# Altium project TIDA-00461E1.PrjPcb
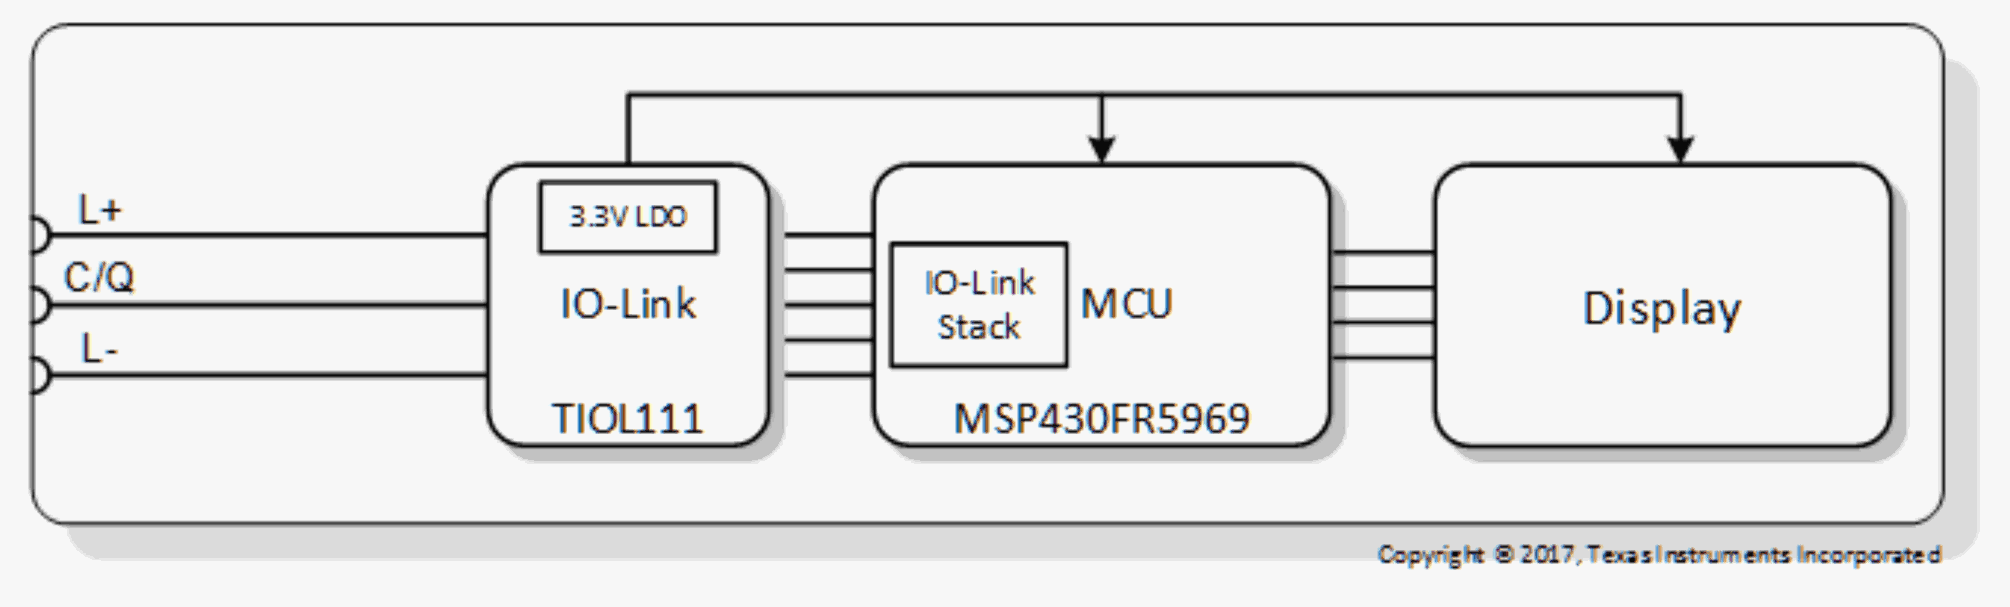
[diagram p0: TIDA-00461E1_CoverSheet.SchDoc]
CopyrightYear: 2016; PCB_Layout: AW; PCB_Rev: E1; PRJ_Customer: Public Release; PRJ_Engineer: AW; PRJ_Number: TIDA-00461; PRJ_Title: IO-Link Firmware Update Reference Design; SCH_Rev: E1; TechSupport: http://www.ti.com/support; TID: TIDA-00461
3 sheets, 79 parts. Net scope: flat (ports and power ports of the same name join across sheets).
Board file: TIDA-00461E1_PCB.PcbDoc
Sheets:
  TIDA-00461E1_CoverSheet.SchDoc
  TIDA-00461E1_Schematic.SchDoc
  TIDA-00461E1_EVM_Hardware.SchDoc

## Sheet TIDA-00461E1_CoverSheet.SchDoc: Block Diagram
size 431 x 279 mm; Date: Not shown in title block; ApprovedBy: Not shown in title block; CheckedBy: Not shown in title block; Author: Not shown in title block; CompanyName: Not shown in title block; DrawnBy: AW; Engineer: Not shown in title block; Organization: Not shown in title block; Address1: Not shown in title block; Address2: Not shown in title block; Address3: Not shown in title block; Address4: Not shown in title block; DocumentNumber: 1; Revision: Use project parameter SCH_Rev; SheetNumber: 1; SheetTotal: 3; PageSetup: Record=PageOptions¦CenterHorizontal=True¦CenterVertical=True¦PrintScale=1.00¦XCorrection=1.00¦YCorrection=1.00¦PrintKind=0¦BorderSize=5000000¦LeftOffset=0¦BottomOffset=0¦Orientation=2¦PaperLength=1000¦PaperWidth=1000¦Scale=100¦PaperSource=15¦PrintQuality=600¦MediaType=1¦DitherType=10¦PaperKind=Letter¦PrintScaleMode=1

## Sheet TIDA-00461E1_Schematic.SchDoc: Schematic
size 431 x 279 mm; Date: Not shown in title block; ApprovedBy: Not shown in title block; CheckedBy: Not shown in title block; Author: Not shown in title block; CompanyName: Not shown in title block; DrawnBy: AW; Engineer: Not shown in title block; Organization: Not shown in title block; Address1: Not shown in title block; Address2: Not shown in title block; Address3: Not shown in title block; Address4: Not shown in title block; DocumentNumber: 2; Revision: Use project parameter SCH_Rev; SheetNumber: 2; SheetTotal: 3; PageSetup: Record=PageOptions¦CenterHorizontal=True¦CenterVertical=True¦PrintScale=1.00¦XCorrection=1.00¦YCorrection=1.00¦PrintKind=0¦BorderSize=5000000¦LeftOffset=0¦BottomOffset=0¦Orientation=2¦PaperLength=1000¦PaperWidth=1000¦Scale=100¦PaperSource=15¦PrintQuality=600¦MediaType=1¦DitherType=10¦PaperKind=Letter¦PrintScaleMode=1
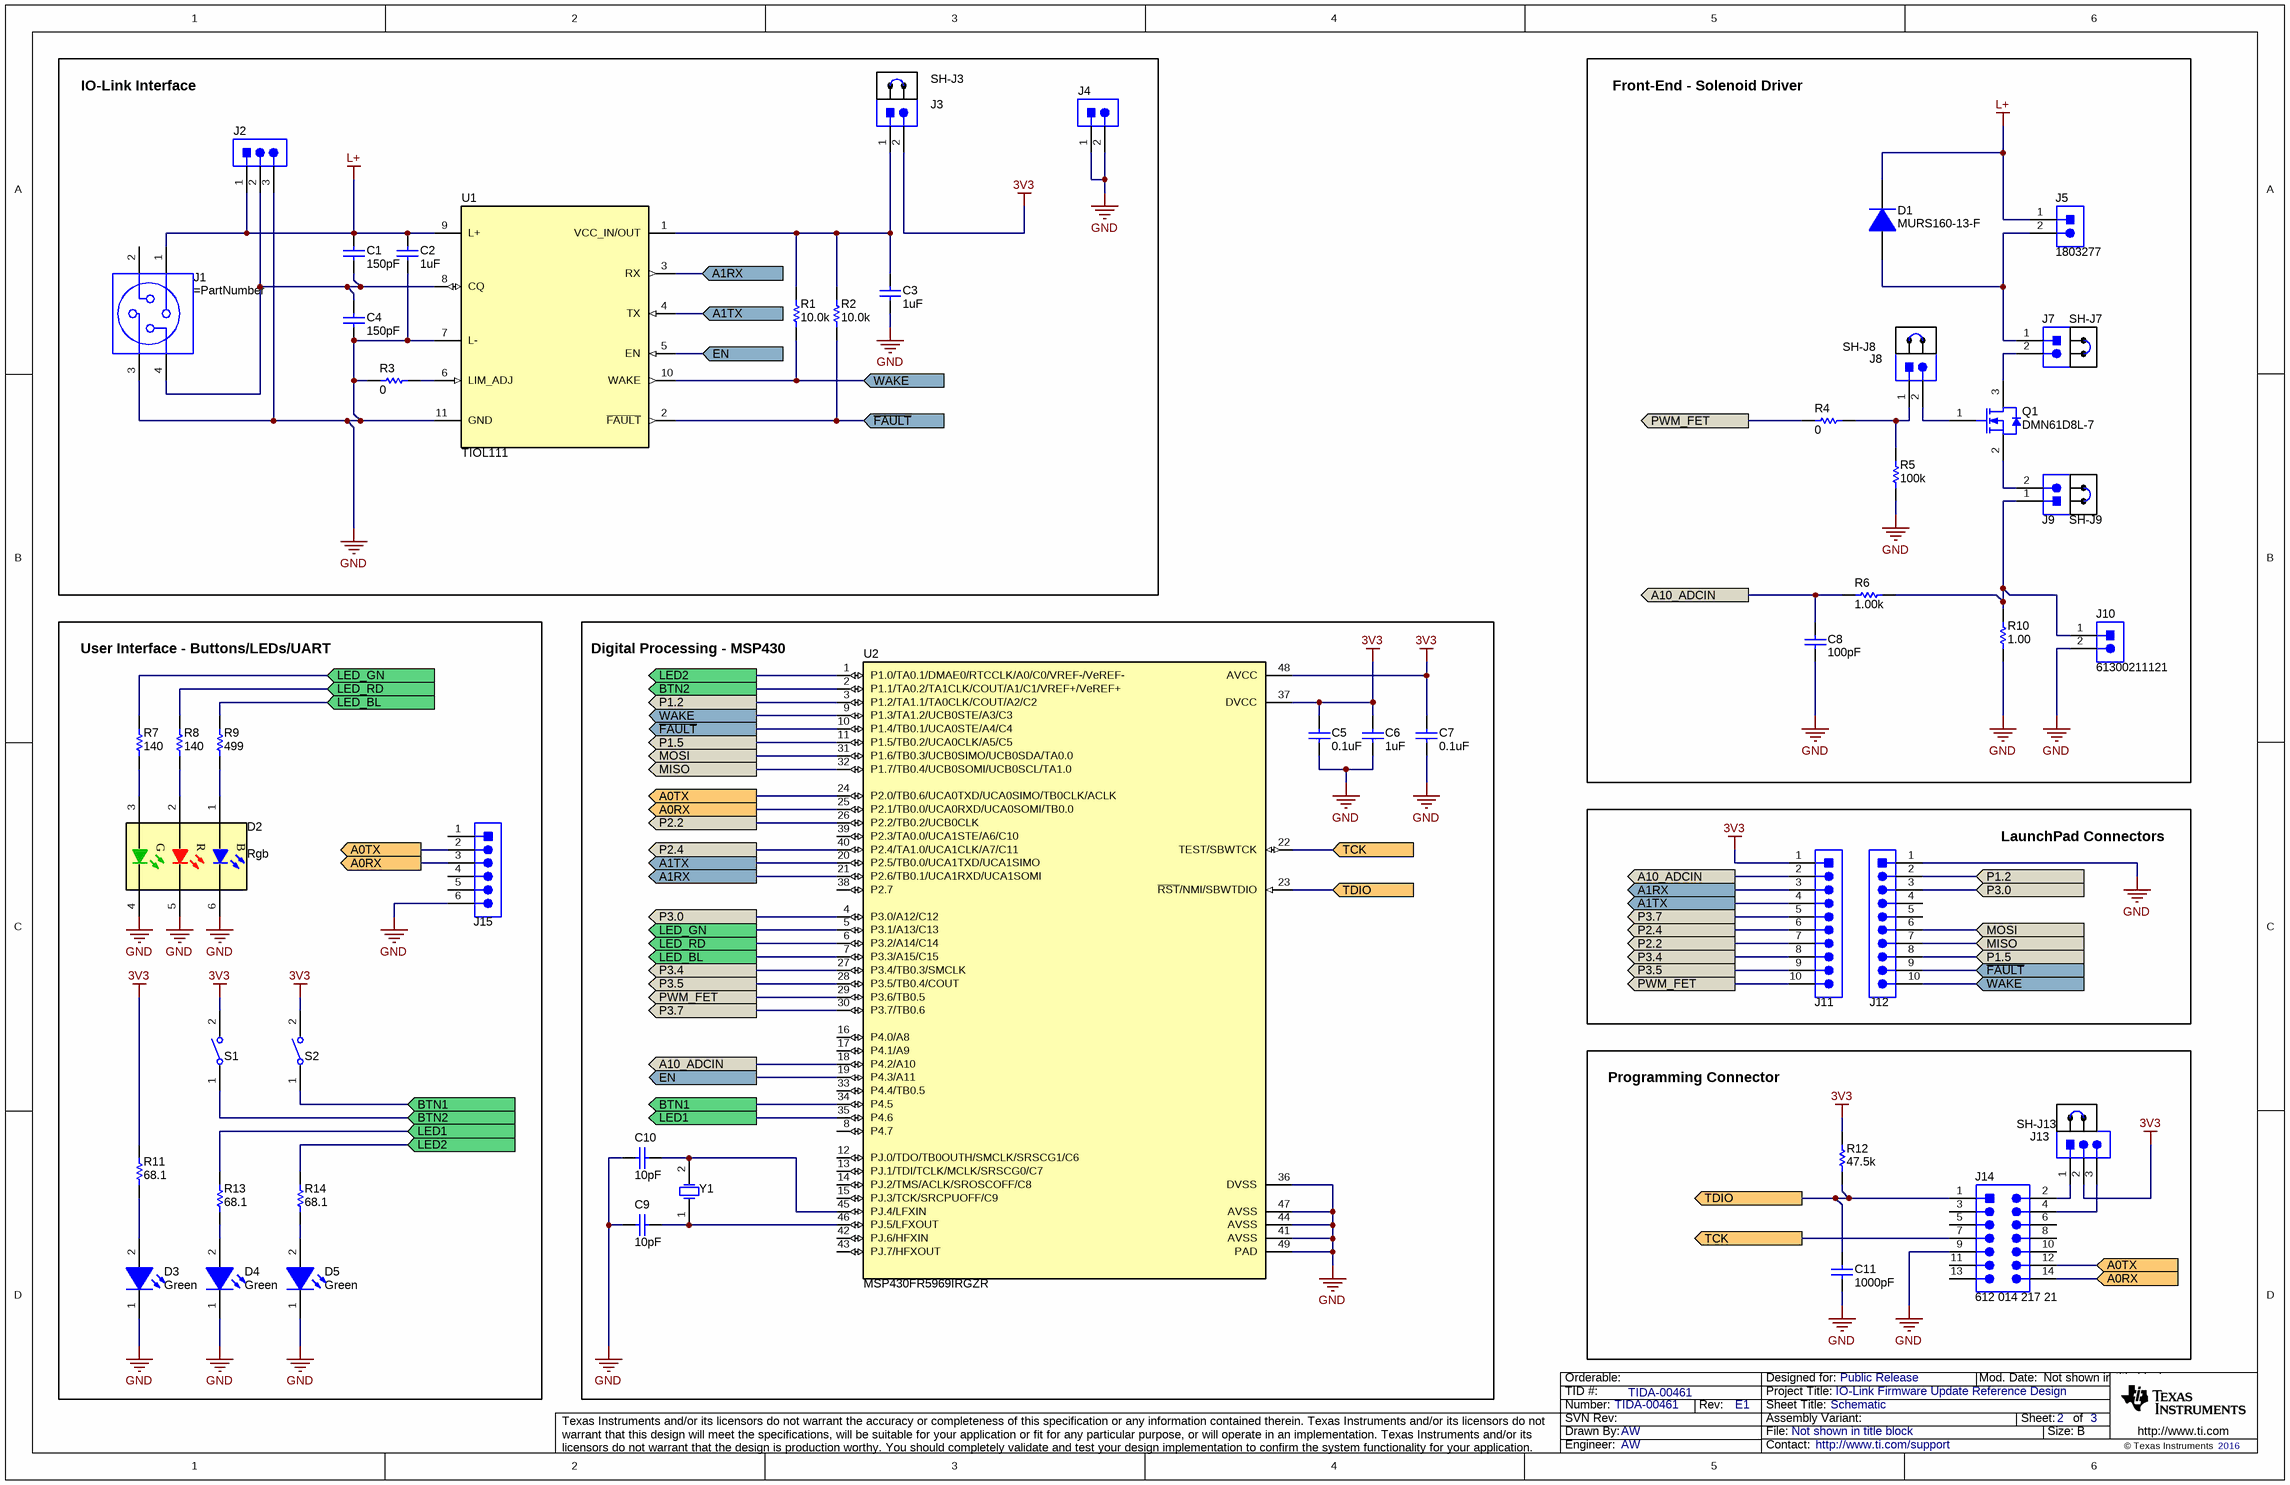
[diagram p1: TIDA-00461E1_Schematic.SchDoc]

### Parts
C1  ValueDisplayed: 150pF  [0402S]  (hidden comment: GRM1555C1H151JA01D)
C2  ValueDisplayed: 1uF  [0805_HV1]  (hidden comment: CGA4J3X7S2A105K125AB)
C3  ValueDisplayed: 1uF  [0402S]  (hidden comment: GRM155R61A105KE15D)
C4  ValueDisplayed: 150pF  [0402S]  (hidden comment: GRM1555C1H151JA01D)
C5  ValueDisplayed: 0.1uF  [0402]  (hidden comment: GRM155R71C104JA88D)
C6  ValueDisplayed: 1uF  [0402]  (hidden comment: GRM155R61A105KE15D)
C7  ValueDisplayed: 0.1uF  [0402]  (hidden comment: GRM155R71C104JA88D)
C8  ValueDisplayed: 100pF  [0603]  (hidden comment: GRM1885C1H101JA01D)
C9  ValueDisplayed: 10pF  [0402]  (hidden comment: GRM1555C1H100RA01D)
C10  ValueDisplayed: 10pF  [0402]  (hidden comment: GRM1555C1H100RA01D)
C11  ValueDisplayed: 1000pF  [0402S]  (hidden comment: 885012205061)
D1  MURS160-13-F  [SMB]
D2  value Rgb  [PicoLED_RGB_150x100]  (hidden comment: SMLP36RGB2W3)
D3  value Green  [WL-SMCW_GREEN]  (hidden comment: 150060VS75000)
D4  value Green  [WL-SMCW_GREEN]  (hidden comment: 150060VS75000)
D5  value Green  [WL-SMCW_GREEN]  (hidden comment: 150060VS75000)
J1  (no value)  [Conec_43-01205]
J2  61300311121  [WURTH_61300311121]  (value not drawn)
J3  61300211121  [WURTH_61300211121]  (value not drawn)
J4  61300211121  [WURTH_61300211121]  (value not drawn)
J5  1803277  [PhoenixContact_1803277]
J7  61300211121  [WURTH_61300211121]  (value not drawn)
J8  61300211121  [WURTH_61300211121]  (value not drawn)
J9  61300211121  [WURTH_61300211121]  (value not drawn)
J10  61300211121  [WURTH_61300211121]
J11  61301011121  [Wurth_61301011121]  (value not drawn)
J12  61301011121  [Wurth_61301011121]  (value not drawn)
J13  61300311121  [WURTH_61300311121]  (value not drawn)
J14  612 014 217 21  [WURTH_612_014_217_21_Correct]
J15  61300611121  [WURTH_61300611121]  (value not drawn)
Q1  DMN61D8L-7  [SOT-23]
R1  ValueDisplayed: 10.0k  [0201]  (hidden comment: CRCW020110K0FKED)
R2  ValueDisplayed: 10.0k  [0201]  (hidden comment: CRCW020110K0FKED)
R3  ValueDisplayed: 0  [0402]  (hidden comment: CRCW04020000Z0ED)
R4  ValueDisplayed: 0  [0603]  (hidden comment: CRCW06030000Z0EA)
R5  ValueDisplayed: 100k  [0603]  (hidden comment: CRCW0603100KFKEA)
R6  ValueDisplayed: 1.00k  [0603]  (hidden comment: CRCW06031K00FKEA)
R7  ValueDisplayed: 140  [0402S]  (hidden comment: CRCW0402140RFKED)
R8  ValueDisplayed: 140  [0402S]  (hidden comment: CRCW0402140RFKED)
R9  ValueDisplayed: 499  [0402S]  (hidden comment: CRCW0402499RFKED)
R10  ValueDisplayed: 1.00  [2512]  (hidden comment: CRCW25121R00FNEG)
R11  ValueDisplayed: 68.1  [0402]  (hidden comment: CRCW040268R1FKED)
R12  ValueDisplayed: 47.5k  [0603_HV]  (hidden comment: CRCW060347K5FKEA)
R13  ValueDisplayed: 68.1  [0402]  (hidden comment: CRCW040268R1FKED)
R14  ValueDisplayed: 68.1  [0402]  (hidden comment: CRCW040268R1FKED)
S1  434121025816  [SW_434121025816]  (value not drawn)
S2  434121025816  [SW_434121025816]  (value not drawn)
SH-J3  60900213421  [Wurth_60900213421]  (value not drawn)
SH-J7  60900213421  [Wurth_60900213421]  (value not drawn)
SH-J8  60900213421  [Wurth_60900213421]  (value not drawn)
SH-J9  60900213421  [Wurth_60900213421]  (value not drawn)
SH-J13  60900213421  [Wurth_60900213421]  (value not drawn)
U1  TIOL111  [TIOL111]
U2  MSP430FR5969IRGZR  [RGZ0048B]
Y1  MS3V-T1R 32.768KHZ 7.0 PF  [XTAL_MS3V-T1R]  (value not drawn)

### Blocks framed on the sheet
IO-Link Interface: C1-C4 J1-J4 R1-R3 SH-J3 U1
Front-End - Solenoid Driver: C8 D1 J5 J7-J10 Q1 R4-R6 R10 SH-J7-SH-J9
User Interface - Buttons/LEDs/UART: D2-D5 J15 R7-R9 R11 R13 R14 S1 S2
Digital Processing - MSP430: C5-C7 C9 C10 U2 Y1
LaunchPad Connectors: J11 J12
Programming Connector: C11 J13 J14 R12 SH-J13

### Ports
A0RX, A0TX, A1RX, A1TX, A10_ADCIN, BTN1, BTN2, EN, LED1, LED2, LED_BL, LED_GN, LED_RD, MISO, MOSI, P1.2, P1.5, P2.2, P2.4, P3.0, P3.4, P3.5, P3.7, PWM_FET, TCK, TDIO, WAKE, ~{FAULT}

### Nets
3V3: C5.1 C6.1 C7.1 J3.2 J11.1 J13.2 R11.1 R12.2 S1.2 S2.2 U2.37(DVCC) U2.48(AVCC)
GND: C2.2 C3.2 C4.2 C5.2 C6.2 C7.2 C8.2 C9.2 C10.2 C11.2 D2.4 D2.5 D2.6 D3.1(K) D4.1(K) D5.1(K) J1.3 J2.3 J4.1 J4.2 J10.2 J12.1 J14.9 J15.6 R3.2 R5.1 R10.1 U1.7(L-) U1.11(GND) U2.36(DVSS) U2.41(AVSS) U2.44(AVSS) U2.47(AVSS) U2.49(PAD)
L+: C1.1 C2.1 D1.1(K) J1.1 J2.1 J5.1 U1.9(L+)
~{FAULT}: J12.9 R2.1 U1.2(~{FAULT}) U2.10(P1.4/TB0.1/UCA0STE/A4/C4) ; port ~{FAULT}
A0RX: J14.14 J15.3 U2.25(P2.1/TB0.0/UCA0RXD/UCA0SOMI/TB0.0) ; port A0RX
A0TX: J14.12 J15.2 U2.24(P2.0/TB0.6/UCA0TXD/UCA0SIMO/TB0CLK/ACLK) ; port A0TX
A1RX: J11.3 U1.3(RX) U2.21(P2.6/TB0.1/UCA1RXD/UCA1SOMI) ; port A1RX
A1TX: J11.4 U1.4(TX) U2.20(P2.5/TB0.0/UCA1TXD/UCA1SIMO) ; port A1TX
A10_ADCIN: C8.1 J11.2 R6.1 U2.18(P4.2/A10) ; port A10_ADCIN
BTN1: S2.1 U2.34(P4.5) ; port BTN1
BTN2: S1.1 U2.2(P1.1/TA0.2/TA1CLK/COUT/A1/C1/VREF+/VeREF+) ; port BTN2
EN: U1.5(EN) U2.19(P4.3/A11) ; port EN
LED1: R13.1 U2.35(P4.6) ; port LED1
LED2: R14.1 U2.1(P1.0/TA0.1/DMAE0/RTCCLK/A0/C0/VREF-/VeREF-) ; port LED2
LED_BL: R9.1 U2.7(P3.3/A15/C15) ; port LED_BL
LED_GN: R7.1 U2.5(P3.1/A13/C13) ; port LED_GN
LED_RD: R8.1 U2.6(P3.2/A14/C14) ; port LED_RD
MISO: J12.7 U2.32(P1.7/TB0.4/UCB0SOMI/UCB0SCL/TA1.0) ; port MISO
MOSI: J12.6 U2.31(P1.6/TB0.3/UCB0SIMO/UCB0SDA/TA0.0) ; port MOSI
P1.2: J12.2 U2.3(P1.2/TA1.1/TA0CLK/COUT/A2/C2) ; port P1.2
P1.5: J12.8 U2.11(P1.5/TB0.2/UCA0CLK/A5/C5) ; port P1.5
P2.2: J11.7 U2.26(P2.2/TB0.2/UCB0CLK) ; port P2.2
P2.4: J11.6 U2.40(P2.4/TA1.0/UCA1CLK/A7/C11) ; port P2.4
P3.0: J12.3 U2.4(P3.0/A12/C12) ; port P3.0
P3.4: J11.8 U2.27(P3.4/TB0.3/SMCLK) ; port P3.4
P3.5: J11.9 U2.28(P3.5/TB0.4/COUT) ; port P3.5
P3.7: J11.5 U2.30(P3.7/TB0.6) ; port P3.7
PWM_FET: J11.10 R4.1 U2.29(P3.6/TB0.5) ; port PWM_FET
TCK: J14.7 U2.22(TEST/SBWTCK) ; port TCK
TDIO: C11.1 J14.1 R12.1 U2.23(~{RST}/NMI/SBWTDIO) ; port TDIO
WAKE: J12.10 R1.1 U1.10(WAKE) U2.9(P1.3/TA1.2/UCB0STE/A3/C3) ; port WAKE
NetC1_2: C1.2 C4.1 J1.4 J2.2 U1.8(CQ)
NetC3_1: C3.1 J3.1 R1.2 R2.2 U1.1(VCC_IN/OUT)
NetC9_1: C9.1 U2.46(PJ.5/LFXOUT) Y1.1(OSC1)
NetC10_1: C10.1 U2.45(PJ.4/LFXIN) Y1.2(OSC2)
NetD1_2: D1.2(A) J5.2 J7.1
NetD2_1: D2.1(A) R9.2
NetD2_2: D2.2 R8.2
NetD2_3: D2.3 R7.2
NetD3_2: D3.2(A) R11.2
NetD4_2: D4.2(A) R13.2
NetD5_2: D5.2(A) R14.2
NetJ7_2: J7.2 Q1.3(D)
NetJ8_1: J8.1 R4.2 R5.2
NetJ8_2: J8.2 Q1.1(G)
NetJ9_1: J9.1 J10.1 R6.2 R10.2
NetJ9_2: J9.2 Q1.2(S)
NetJ13_1: J13.1 J14.2
NetJ13_3: J13.3 J14.4
NetR3_1: R3.1 U1.6(LIM_ADJ)

Not connected (* = marked no-connect by the designer): J1 2; J12 4 5; J14 3 5 6 8 10 11 13; J15 1 4 5; U2 8(P4.7) 12(PJ.0/TDO/TB0OUTH/SMCLK/SRSCG1/C6) 13(PJ.1/TDI/TCLK/MCLK/SRSCG0/C7) 14(PJ.2/TMS/ACLK/SROSCOFF/C8) 15(PJ.3/TCK/SRCPUOFF/C9) 16(P4.0/A8) 17(P4.1/A9) 33(P4.4/TB0.5) 38(P2.7) 39(P2.3/TA0.0/UCA1STE/A6/C10) 42(PJ.6/HFXIN) 43(PJ.7/HFXOUT)

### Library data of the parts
C1 C4 = CMP-0006421-1: CAP, CERM, 150 pF, 50 V, +/- 5%, C0G/NP0, 0402; Manufacturer: MuRata; Polarized: N; Value: 150pF; U/M: EA; Value1: Unknown; VDC_V: 50V; TaMin_C: -55°C; TaMax_C: 125°C; Cap_Case: 0402; SizeArea_mm2: 0.5; SizeAreaWB_mm2: 3; SizeX_mm: 1; SizeZ_mm: 0.6; AEC Category: Q200
C2 = CMP-0007980-2: CAP, CERM, 1 uF, 100 V, +/- 10%, X7S, AEC-Q200 Grade 1, 0805; Manufacturer: TDK; Polarized: N; Value: 1uF; U/M: EA; Cap_F: 1µF; ESR_ohm: 8.255m; Value1: 0.008255 ohm; VDC_V: 100V; IRMS_A: 2.27442A; TaMin_C: -55°C; TaMax_C: 125°C; Cap_Case: 0805; SizeArea_mm2: 2.5; SizeAreaWB_mm2: 6.75; SizeX_mm: 2; SizeY_mm: 1.25; SizeZ_mm: 1.45; AEC Category: Q200; AEC Qualified: Y; AEC Grade: 1
C3 = CMP-0006563-2: CAP, CERM, 1 uF, 10 V, +/- 10%, X5R, 0402; Manufacturer: MuRata; Polarized: N; Value: 1uF; U/M: EA; Cap_F: 1µF; Value1: Unknown; VDC_V: 10V; TaMin_C: -55°C; TaMax_C: 85°C; Cap_Case: 0402; SizeArea_mm2: 0.5; SizeAreaWB_mm2: 3; SizeX_mm: 1; SizeZ_mm: 0.6; AEC Category: Q200
C5 C7 = CMP-0006640-2: CAP, CERM, 0.1 uF, 16 V, +/- 5%, X7R, 0402; Manufacturer: MuRata; Polarized: N; Value: 0.1uF; U/M: EA; Cap_F: 100nF; Value1: Unknown; VDC_V: 16V; TaMin_C: -55°C; TaMax_C: 125°C; SizeArea_mm2: 0.5; SizeAreaWB_mm2: 3; SizeX_mm: 1; SizeZ_mm: 0.6; AEC Category: Q200
C6 = CMP-0006563-2: CAP, CERM, 1 uF, 10 V, +/- 10%, X5R, 0402; Manufacturer: MuRata; Polarized: N; Value: 1uF; U/M: EA; Cap_F: 1µF; Value1: Unknown; VDC_V: 10V; TaMin_C: -55°C; TaMax_C: 85°C; SizeArea_mm2: 0.5; SizeAreaWB_mm2: 3; SizeX_mm: 1; SizeZ_mm: 0.6; AEC Category: Q200
C8 = CMP-0007171-1: CAP, CERM, 100 pF, 50 V, +/- 5%, C0G/NP0, 0603; Manufacturer: MuRata; Polarized: N; Value: 100pF; U/M: EA; Value1: Unknown; VDC_V: 50V; TaMin_C: -55°C; TaMax_C: 125°C; SizeArea_mm2: 1.28; SizeAreaWB_mm2: 4.68; SizeX_mm: 1.6; SizeY_mm: 0.8; SizeZ_mm: 1; AEC Category: Q200
C9 C10 = CMP-0006409-1: CAP, CERM, 10 pF, 50 V, +/- 4%, C0G/NP0, 0402; Manufacturer: MuRata; Polarized: N; Value: 10pF; U/M: EA; Value1: Unknown; VDC_V: 50V; TaMin_C: -55°C; TaMax_C: 125°C; SizeArea_mm2: 0.5; SizeAreaWB_mm2: 3; SizeX_mm: 1; SizeZ_mm: 0.6; AEC Category: Q200
C11 = CMP-0006231-2: CAP, CERM, 1000 pF, 50 V, +/- 10%, X7R, 0402; Manufacturer: Wurth Elektronik; Polarized: N; Value: 1000pF; U/M: EA; Cap_F: 1nF; Value1: Unknown; VDC_V: 50V; TaMin_C: -55°C; TaMax_C: 125°C; Cap_Case: 0402; SizeArea_mm2: 0.5; SizeAreaWB_mm2: 3; SizeX_mm: 1; SizeZ_mm: 0.6; AEC Category: Q200
D1 = CMP-0029028-1: Diode, Ultrafast, 600 V, 1 A, SMB; Manufacturer: Diodes Inc.; U/M: EA; Vf_V: 1.25V; Value: 600V; Value1: 1A; TJmax_C: 150°C; RJC_CperW: 13; SizeAreaWB_mm2: 44.156; SizeArea_mm2: 21.336; SizeX_mm: 5.6; SizeY_mm: 3.81; SizeZ_mm: 2.6; AEC Category: Q101; Green_Lifecycle: Active; Green_REACh: Passed
D2 = CMP-0002932-2: LED, Rgb, SMD; Manufacturer: Rohm; Vf_V: 3.1V; Io_A: 5mA; Vr_V: 5V; Ir_A: 10µA; Tjmax_C: 85°C; Value1: W; U/M: EA
D3-D5 = CMP-0002894-1: LED, Green, SMD; Manufacturer: Wurth Elektronik; Type: AlInGaP; Vf_V: 2V; Io_A: 20mA; Value1: W; U/M: EA
J1 = 43-01205: M12 Socket, Backmounting, 4Pos, Gold, R/A, TH; Available Preview Images: 2D
J2 J13 = CMP-0054796-1: Header, 2.54 mm, 3x1, Gold, TH; Manufacturer: Wurth Elektronik; CNHeader: TRUE; CT: FALSE; Green_Lifecycle: Active; Green_REACh: Passed
J3 J4 J7-J10 = CMP-0054794-1: Header, 2.54 mm, 2x1, Gold, TH; Manufacturer: Wurth Elektronik; CNHeader: TRUE; CT: FALSE; Green_Lifecycle: Active; Green_REACh: Passed
J5 = CMP-0055494-1: Terminal Block, 2x1, 3.81mm, R/A, TH; Manufacturer: Phoenix Contact; CNHeader: FALSE; CT: TRUE
J11 J12 = CMP-0054804-1: Header, 2.54mm, 10x1, Gold, TH; Manufacturer: Wurth Elektronik; Pitch_mm: 2.54; Gender: Male; Shrouded: N; Row_Count: 1; CNHeader: TRUE; CT: FALSE
J14 = CMP-0054781-1: Header (Shrouded), 2.54 mm, 7x2, Gold, R/A, TH; Manufacturer: Wurth Elektronik; CNHeader: FALSE
J15 = CMP-0054801-1: Header, 2.54 mm, 6x1, Gold, TH; Manufacturer: Wurth Elektronik; CNHeader: TRUE; CT: FALSE
Q1 = CMP-0000830-1: MOSFET, N-CH, 60 V, 0.47 A, AEC-Q101, SOT-23; Manufacturer: Diodes Inc.; Alternate Manufacturer: None; U/M: EA; ChType: N; Value: 60V; Value2: 0.74 nC; QgTyp_nC: 0.74; Vgs_V: 12V; IdsMax_A: 4.7dA; SizeAreaWB_mm2: 14; SizeArea_mm2: 7.5; SizeX_mm: 2.5; SizeY_mm: 3; SizeZ_mm: 1.1; AEC Category: Q101; AEC Qualified: Y
R1 R2 = CMP-0027262-1: RES, 10.0 k, 1%, 0.05 W, 0201; Manufacturer: Vishay-Dale; Value: 10.0k; Res_ohm: 10k; Value_Code: 10k0; Power_W: 50mW; Value2: 0.05W; VDC_V: 30V; TempCo: 100 ppm/C; SizeArea_mm2: 0.18; SizeX_mm: 0.6; SizeY_mm: 0.3; SizeZ_mm: 0.26; EIA_Code: E96; U/M: EA; AEC Category: Q200; AEC Qualified: N
R3 = CMP-0026822-1: RES, 0, 5%, 0.063 W, 0402; Manufacturer: Vishay-Dale; Value: 0; Value_Code: 0000; Power_W: 63mW; Value2: 0.063W; VDC_V: 50V; TempCo: 200 ppm/C; SizeArea_mm2: 0.5; SizeX_mm: 1; SizeZ_mm: 0.6; EIA_Code: E24; U/M: EA; AEC Category: Q200
R4 = CMP-0025697-1: RES, 0, 5%, 0.1 W, 0603; Manufacturer: Vishay-Dale; Value: 0; Value_Code: 0000; Power_W: 100mW; Value2: 0.1W; VDC_V: 75V; TempCo: 200 ppm/C; SizeArea_mm2: 1.28; SizeX_mm: 1.6; SizeY_mm: 0.8; SizeZ_mm: 1; EIA_Code: E24; U/M: EA; AEC Category: Q200
R5 = CMP-0021990-1: RES, 100 k, 1%, 0.1 W, 0603; Manufacturer: Vishay-Dale; Value: 100k; Power_W: 100mW; Value2: 0.1W; VDC_V: 75V; TempCo: 100 ppm/C; SizeArea_mm2: 1.28; SizeX_mm: 1.6; SizeY_mm: 0.8; SizeZ_mm: 1; EIA_Code: E96; U/M: EA; AEC Category: Q200
R6 = CMP-0022109-2: RES, 1.00 k, 1%, 0.1 W, 0603; Manufacturer: Vishay-Dale; Value: 1.00k; Res_ohm: 1k; Value_Code: 1k00; Power_W: 100mW; Value2: 0.1W; VDC_V: 75V; TempCo: 100 ppm/C; SizeArea_mm2: 1.28; SizeX_mm: 1.6; SizeY_mm: 0.8; SizeZ_mm: 1; EIA_Code: E96; U/M: EA; AEC Category: Q200
R7 R8 = CMP-0026010-2: RES, 140, 1%, 0.063 W, 0402; Manufacturer: Vishay-Dale; Value: 140; Value_Code: 140R; Power_W: 63mW; Value2: 0.063W; VDC_V: 50V; TempCo: 100 ppm/C; SizeArea_mm2: 0.5; SizeX_mm: 1; SizeZ_mm: 0.6; EIA_Code: E96; U/M: EA; AEC Category: Q200
R9 = CMP-0026402-1: RES, 499, 1%, 0.063 W, 0402; Manufacturer: Vishay-Dale; Value: 499; Value_Code: 499R; Power_W: 63mW; Value2: 0.063W; VDC_V: 50V; TempCo: 100 ppm/C; SizeArea_mm2: 0.5; SizeX_mm: 1; SizeZ_mm: 0.6; EIA_Code: E96; U/M: EA; AEC Category: Q200
R10 = CMP-0015520-1: RES, 1.00, 1%, 1 W, AEC-Q200 Grade 0, 2512; Manufacturer: Vishay-Dale; Value: 1.00; Res_ohm: 1; Value_Code: 1R00; Power_W: 1W; VDC_V: 500V; TempCo: 200 ppm/C; SizeArea_mm2: 20.16; SizeX_mm: 6.3; SizeY_mm: 3.2; SizeZ_mm: 0.71; EIA_Code: E96; U/M: EA; AEC Category: Q200; AEC Qualified: Y; AEC Grade: 0
R11 R13 R14 = CMP-0026507-1: RES, 68.1, 1%, 0.063 W, 0402; Manufacturer: Vishay-Dale; Value: 68.1; Value_Code: 68R1; Power_W: 63mW; Value2: 0.063W; VDC_V: 50V; TempCo: 100 ppm/C; SizeArea_mm2: 0.5; SizeX_mm: 1; SizeZ_mm: 0.6; EIA_Code: E96; U/M: EA; AEC Category: Q200
R12 = CMP-0022439-1: RES, 47.5 k, 1%, 0.1 W, 0603; Manufacturer: Vishay-Dale; Value: 47.5k; Value_Code: 47k5; Power_W: 100mW; Value2: 0.1W; VDC_V: 75V; TempCo: 100 ppm/C; SizeArea_mm2: 1.28; SizeX_mm: 1.6; SizeY_mm: 0.8; SizeZ_mm: 1; EIA_Code: E96; U/M: EA; AEC Category: Q200
S1 S2 = CMP-0002196-1: Switch, Tactile, SPST, 12 V, SMD; Manufacturer: Wurth Elektronik; VDC_V: 12V; SwitchFunction: Off-On; PositionCount: 1; CurrentRating_mA: 50A
SH-J3 SH-J7-SH-J9 SH-J13 = CMP-0003761-1: Shunt, 2.54mm, Gold, Black; Manufacturer: Wurth Elektronik
U1 = CMP-0014126-1: IO-Link Device Transceiver with Integrated Surge Protection, TIOL111 (WSON-10); Manufacturer: Texas Instruments; SizeArea_mm2: 7.5; SizeAreaWB_mm2: 14; SizeX_mm: 3; SizeY_mm: 2.5; SizeZ_mm: 1; CompType: IC; U/M: EA
U2 = CMP-0066503-1: MSP430FR5969 16 MHz Ultra-Low-Power Microcontroller featuring 64 KB FRAM, 2 KB SRAM, 40 IO, RGZ0048B (VQFN-48); Alternate PartNumber: MSP430FR5969IRGZT; Manufacturer: Texas Instruments; SizeArea_mm2: 49.0; SizeAreaWB_mm2: 81.0; SizeX_mm: 7.0; SizeZ_mm: 1.0; CompType: IC; U/M: EA; Green_Lifecycle: Active; Green_REACh: Passed
Y1 = CMP-0004695-1: Crystal, 32.768 KHz, 7pF, SMD; Manufacturer: Micro Crystal AG; U/M: EA; TaMin_C: -40°C; TaMax_C: 85°C

## Sheet TIDA-00461E1_EVM_Hardware.SchDoc: Hardware
size 431 x 279 mm; Date: Not shown in title block; ApprovedBy: Not shown in title block; CheckedBy: Not shown in title block; Author: Not shown in title block; CompanyName: Not shown in title block; DrawnBy: AW; Engineer: Not shown in title block; Organization: Not shown in title block; Address1: Not shown in title block; Address2: Not shown in title block; Address3: Not shown in title block; Address4: Not shown in title block; DocumentNumber: 3; Revision: Use project parameter SCH_Rev; SheetNumber: 3; SheetTotal: 3; PageSetup: Record=PageOptions¦CenterHorizontal=True¦CenterVertical=True¦PrintScale=1.00¦XCorrection=1.00¦YCorrection=1.00¦PrintKind=0¦BorderSize=5000000¦LeftOffset=0¦BottomOffset=0¦Orientation=2¦PaperLength=1000¦PaperWidth=1000¦Scale=100¦PaperSource=15¦PrintQuality=600¦MediaType=1¦DitherType=10¦PaperKind=Letter¦PrintScaleMode=1
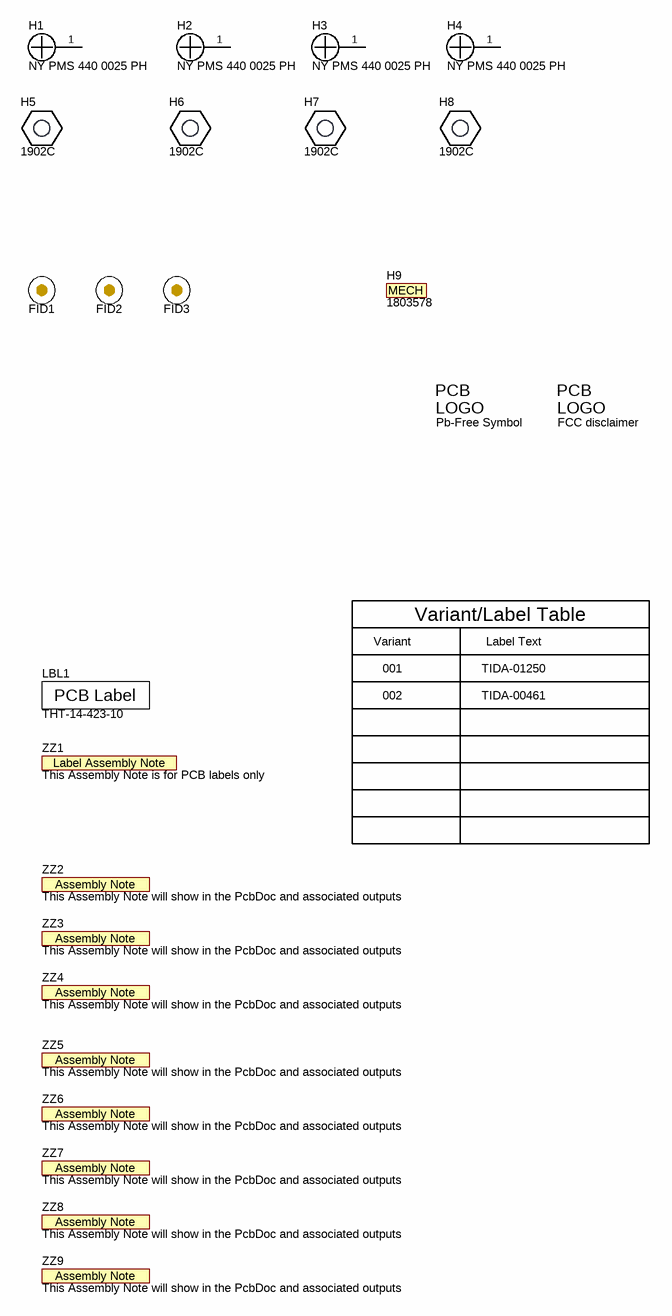
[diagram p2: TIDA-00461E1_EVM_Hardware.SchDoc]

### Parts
FID1  Fiducial  [Fiducial10-20]  (value not drawn)
FID2  Fiducial  [Fiducial10-20]  (value not drawn)
FID3  Fiducial  [Fiducial10-20]  (value not drawn)
H1  NY PMS 440 0025 PH  [NY PMS 440 0025 PH]
H2  NY PMS 440 0025 PH  [NY PMS 440 0025 PH]
H3  NY PMS 440 0025 PH  [NY PMS 440 0025 PH]
H4  NY PMS 440 0025 PH  [NY PMS 440 0025 PH]
H5  1902C  [Keystone_1902C]
H6  1902C  [Keystone_1902C]
H7  1902C  [Keystone_1902C]
H8  1902C  [Keystone_1902C]
H9  1803578  (mechanical)
LBL1  THT-14-423-10  [Label_650x200]
Logo2  Pb-Free Symbol  [Pb-Free_Overlay_Small]  (no BOM)
Logo3  FCC disclaimer  [FCC_disclaimer]  (no BOM)
ZZ1  This Assembly Note is for PCB labels only  [AssemblyNoteLabel]  (no BOM)
ZZ2  This Assembly Note will show in the PcbDoc and associated outputs  [AssemblyNote]  (no BOM)
ZZ3  This Assembly Note will show in the PcbDoc and associated outputs  [AssemblyNote]  (no BOM)
ZZ4  This Assembly Note will show in the PcbDoc and associated outputs  [AssemblyNote]  (no BOM)
ZZ5  This Assembly Note will show in the PcbDoc and associated outputs  [AssemblyNote]  (no BOM)
ZZ6  This Assembly Note will show in the PcbDoc and associated outputs  [AssemblyNote]  (no BOM)
ZZ7  This Assembly Note will show in the PcbDoc and associated outputs  [AssemblyNote]  (no BOM)
ZZ8  This Assembly Note will show in the PcbDoc and associated outputs  [AssemblyNote]  (no BOM)
ZZ9  This Assembly Note will show in the PcbDoc and associated outputs  [AssemblyNote]  (no BOM)

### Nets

Not connected (* = marked no-connect by the designer): H1 1; H2 1; H3 1; H4 1

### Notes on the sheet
- Variant
- Variant/Label Table
- Label Text
- 001
- 002
- TIDA-01250
- TIDA-00461

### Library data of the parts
FID1-FID3 = Fiducial: Fiducial mark.  There is nothing to buy or mount.; SymbolCreator: codlsc
H1-H4 = CMP-0003617-1: Machine Screw, Round, #4-40 x 1/4, Nylon, Philips panhead; Manufacturer: B&F Fastener Supply; CompType: Hardware
H5-H8 = CMP-0003610-1: Standoff, Hex, 0.5"L #4-40 Nylon; Manufacturer: Keystone; CompType: Hardware
H9 = CMP-0003847-1: Terminal Block Plug, 3.81mm, 2x1, Green; Manufacturer: Phoenix Contact; CompType: TERM BLOCK
LBL1 = CMP-0003625-1: Thermal Transfer Printable Labels, 0.650" W x 0.200" H - 10,000 per roll; Manufacturer: Brady; Note: Size: 0.65" x 0.20 "
Logo2 = Pb-Free: SymbolCreator: a0412235
Logo3 = FCC_disclaimer: SymbolCreator: a0412235
ZZ1 = AssemblyNoteLabel: SymbolCreator: a0412235
ZZ2-ZZ9 = AssemblyNote: SymbolCreator: codlsc

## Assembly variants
001: not fitted C11 FID1 FID2 FID3
002: not fitted C8 C11 D1 J5 J7 J8 J9 J10 Q1 R4 R5 R6 R10 SH-J7 SH-J8 SH-J9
